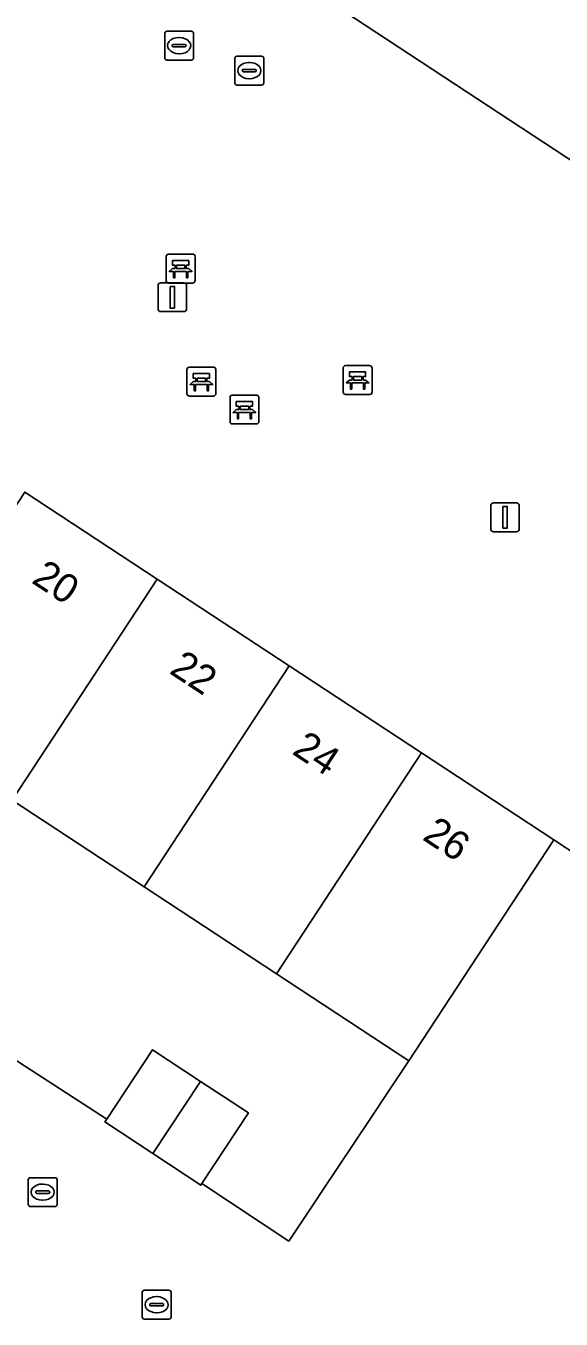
# Model space of a CAD drawing. Extents: x 159279 to 160377, y 384531 to 385888.
# Drawn here: x 159600.5 to 159619.07, y 385070.38 to 385115.23 of the extents above; entities that cross this region are included whole.
import ezdxf

# ---------------------------------------------------------------- set-up
doc = ezdxf.new("R2010")
doc.units = 0
for name, color, linetype in [('IMGEO_Bank', 7, 'Continuous'), ('IMGEO_Erf', 7, 'Continuous'), ('IMGEO_Hek', 7, 'Continuous'), ('IMGEO_Kolk', 7, 'Continuous'), ('IMGEO_Lichtmast', 7, 'Continuous'), ('IMGEO_Pand', 7, 'Continuous'), ('IMGEO_Pand_nummerreeks', 7, 'Continuous'), ('IMGEO_Rioolput', 7, 'Continuous'), ('IMGEO_Voetpad_open', 7, 'Continuous')]:
    doc.layers.add(name, color=color, linetype=linetype)

msp = doc.modelspace()

# ---------------------------------------------------------------- linework, layer by layer
at = {"layer": 'IMGEO_Bank'}
for p, q in [((159605.37, 385106.384), (159605.37, 385107.225)), ((159605.37, 385107.225), (159605.37, 385106.384)), ((159605.445, 385107.309), (159606.286, 385107.309)), ((159606.286, 385107.309), (159605.445, 385107.309)), ((159606.37, 385107.234), (159606.37, 385106.393)), ((159606.37, 385106.393), (159606.37, 385107.234)), ((159606.067, 385106.707), (159605.674, 385106.707)), ((159605.679, 385106.815), (159605.679, 385106.921)), ((159605.723, 385106.921), (159605.723, 385106.815)), ((159606.011, 385106.927), (159605.729, 385106.927)), ((159605.729, 385106.809), (159606.011, 385106.809)), ((159606.017, 385106.815), (159606.017, 385106.921)), ((159606.061, 385106.921), (159606.061, 385106.815)), ((159606.295, 385106.309), (159605.454, 385106.309)), ((159605.454, 385106.309), (159606.295, 385106.309)), ((159606.088, 385102.465), (159606.088, 385103.306)), ((159606.088, 385103.306), (159606.088, 385102.465)), ((159606.163, 385103.39), (159607.004, 385103.39)), ((159607.004, 385103.39), (159606.163, 385103.39)), ((159607.088, 385103.315), (159607.088, 385102.474)), ((159607.088, 385102.474), (159607.088, 385103.315)), ((159611.506, 385102.521), (159611.506, 385103.362)), ((159611.506, 385103.362), (159611.506, 385102.521)), ((159611.581, 385103.446), (159612.422, 385103.446)), ((159612.422, 385103.446), (159611.581, 385103.446)), ((159611.815, 385102.952), (159611.815, 385103.058)), ((159611.859, 385103.058), (159611.859, 385102.952)), ((159612.147, 385103.064), (159611.865, 385103.064)), ((159612.153, 385102.952), (159612.153, 385103.058)), ((159612.197, 385103.058), (159612.197, 385102.952)), ((159612.506, 385103.371), (159612.506, 385102.53)), ((159612.506, 385102.53), (159612.506, 385103.371)), ((159606.785, 385102.788), (159606.392, 385102.788)), ((159606.397, 385102.896), (159606.397, 385103.002)), ((159606.441, 385103.002), (159606.441, 385102.896)), ((159606.729, 385103.008), (159606.447, 385103.008)), ((159606.447, 385102.89), (159606.729, 385102.89)), ((159606.735, 385102.896), (159606.735, 385103.002)), ((159606.779, 385103.002), (159606.779, 385102.896)), ((159612.203, 385102.844), (159611.81, 385102.844)), ((159611.865, 385102.946), (159612.147, 385102.946)), ((159607.013, 385102.39), (159606.172, 385102.39)), ((159606.172, 385102.39), (159607.013, 385102.39)), ((159607.581, 385101.496), (159607.581, 385102.337)), ((159607.581, 385102.337), (159607.581, 385101.496)), ((159607.656, 385102.421), (159608.497, 385102.421)), ((159608.497, 385102.421), (159607.656, 385102.421)), ((159608.581, 385102.346), (159608.581, 385101.505)), ((159608.581, 385101.505), (159608.581, 385102.346)), ((159612.431, 385102.446), (159611.59, 385102.446)), ((159611.59, 385102.446), (159612.431, 385102.446)), ((159608.278, 385101.819), (159607.885, 385101.819)), ((159607.89, 385101.927), (159607.89, 385102.033)), ((159607.934, 385102.033), (159607.934, 385101.927)), ((159608.222, 385102.039), (159607.94, 385102.039)), ((159607.94, 385101.921), (159608.222, 385101.921)), ((159608.228, 385101.927), (159608.228, 385102.033)), ((159608.272, 385102.033), (159608.272, 385101.927)), ((159608.506, 385101.421), (159607.665, 385101.421)), ((159607.665, 385101.421), (159608.506, 385101.421))]:
    msp.add_line(p, q, dxfattribs=at)
for points in [[(159605.673, 385106.927), (159605.587, 385106.927), (159605.587, 385107.088), (159606.15, 385107.088), (159606.15, 385106.927), (159606.067, 385106.927)], [(159605.617, 385106.707), (159605.475, 385106.707), (159605.587, 385106.809), (159605.673, 385106.809)], [(159605.667, 385106.7), (159605.667, 385106.493), (159605.624, 385106.493), (159605.624, 385106.7)], [(159606.067, 385106.809), (159606.15, 385106.809), (159606.262, 385106.707), (159606.123, 385106.707)], [(159606.117, 385106.7), (159606.117, 385106.493), (159606.073, 385106.493), (159606.073, 385106.7)], [(159606.391, 385103.008), (159606.305, 385103.008), (159606.305, 385103.169), (159606.868, 385103.169), (159606.868, 385103.008), (159606.785, 385103.008)], [(159611.809, 385103.064), (159611.723, 385103.064), (159611.723, 385103.225), (159612.286, 385103.225), (159612.286, 385103.064), (159612.203, 385103.064)], [(159606.335, 385102.788), (159606.193, 385102.788), (159606.305, 385102.89), (159606.391, 385102.89)], [(159606.385, 385102.781), (159606.385, 385102.574), (159606.342, 385102.574), (159606.342, 385102.781)], [(159606.785, 385102.89), (159606.868, 385102.89), (159606.98, 385102.788), (159606.841, 385102.788)], [(159606.835, 385102.781), (159606.835, 385102.574), (159606.791, 385102.574), (159606.791, 385102.781)], [(159611.753, 385102.844), (159611.611, 385102.844), (159611.723, 385102.946), (159611.809, 385102.946)], [(159611.803, 385102.837), (159611.803, 385102.63), (159611.76, 385102.63), (159611.76, 385102.837)], [(159612.203, 385102.946), (159612.286, 385102.946), (159612.398, 385102.844), (159612.259, 385102.844)], [(159612.253, 385102.837), (159612.253, 385102.63), (159612.209, 385102.63), (159612.209, 385102.837)], [(159607.884, 385102.039), (159607.798, 385102.039), (159607.798, 385102.2), (159608.361, 385102.2), (159608.361, 385102.039), (159608.278, 385102.039)], [(159607.828, 385101.819), (159607.686, 385101.819), (159607.798, 385101.921), (159607.884, 385101.921)], [(159607.878, 385101.812), (159607.878, 385101.605), (159607.835, 385101.605), (159607.835, 385101.812)], [(159608.278, 385101.921), (159608.361, 385101.921), (159608.473, 385101.819), (159608.334, 385101.819)], [(159608.328, 385101.812), (159608.328, 385101.605), (159608.284, 385101.605), (159608.284, 385101.812)]]:
    msp.add_lwpolyline(points, dxfattribs=at)
for centre, radius, start, end in [((159605.448, 385107.231), 0.0779, 92.4484, 184.2845), ((159605.448, 385107.231), 0.0779, 92.4484, 184.2845), ((159606.292, 385107.231), 0.0779, 2.4484, 94.2845), ((159606.292, 385107.231), 0.0779, 2.4484, 94.2845), ((159605.617, 385106.7), 0.00671, 2.8957, 87.1043), ((159605.674, 385106.7), 0.00671, 92.8957, 177.1043), ((159605.672, 385106.92), 0.00671, 2.8957, 87.1043), ((159605.672, 385106.816), 0.00671, 272.8957, 357.1043), ((159605.729, 385106.92), 0.00671, 92.8957, 177.1043), ((159605.729, 385106.816), 0.00671, 182.8957, 267.1043), ((159606.011, 385106.92), 0.00671, 2.8957, 87.1043), ((159606.011, 385106.816), 0.00671, 272.8957, 357.1043), ((159606.068, 385106.92), 0.00671, 92.8957, 177.1043), ((159606.068, 385106.816), 0.00671, 182.8957, 267.1043), ((159606.066, 385106.7), 0.00671, 2.8957, 87.1043), ((159606.123, 385106.7), 0.00671, 92.8957, 177.1043), ((159605.448, 385106.387), 0.0779, 182.4484, 274.2845), ((159605.448, 385106.387), 0.0779, 182.4484, 274.2845), ((159606.292, 385106.387), 0.0779, 272.4484, 4.2845), ((159606.292, 385106.387), 0.0779, 272.4484, 4.2845), ((159606.166, 385103.312), 0.0779, 92.4484, 184.2845), ((159606.166, 385103.312), 0.0779, 92.4484, 184.2845), ((159607.01, 385103.312), 0.0779, 2.4484, 94.2845), ((159607.01, 385103.312), 0.0779, 2.4484, 94.2845), ((159611.584, 385103.368), 0.0779, 92.4484, 184.2845), ((159611.584, 385103.368), 0.0779, 92.4484, 184.2845), ((159611.808, 385103.057), 0.00671, 2.8957, 87.1043), ((159611.865, 385103.057), 0.00671, 92.8957, 177.1043), ((159612.147, 385103.057), 0.00671, 2.8957, 87.1043), ((159612.204, 385103.057), 0.00671, 92.8957, 177.1043), ((159612.428, 385103.368), 0.0779, 2.4484, 94.2845), ((159612.428, 385103.368), 0.0779, 2.4484, 94.2845), ((159606.335, 385102.781), 0.00671, 2.8957, 87.1043), ((159606.392, 385102.781), 0.00671, 92.8957, 177.1043), ((159606.39, 385103.001), 0.00671, 2.8957, 87.1043), ((159606.39, 385102.897), 0.00671, 272.8957, 357.1043), ((159606.447, 385103.001), 0.00671, 92.8957, 177.1043), ((159606.447, 385102.897), 0.00671, 182.8957, 267.1043), ((159606.729, 385103.001), 0.00671, 2.8957, 87.1043), ((159606.729, 385102.897), 0.00671, 272.8957, 357.1043), ((159606.786, 385103.001), 0.00671, 92.8957, 177.1043), ((159606.786, 385102.897), 0.00671, 182.8957, 267.1043), ((159606.784, 385102.781), 0.00671, 2.8957, 87.1043), ((159606.841, 385102.781), 0.00671, 92.8957, 177.1043), ((159611.753, 385102.837), 0.00671, 2.8957, 87.1043), ((159611.81, 385102.837), 0.00671, 92.8957, 177.1043), ((159611.808, 385102.953), 0.00671, 272.8957, 357.1043), ((159611.865, 385102.953), 0.00671, 182.8957, 267.1043), ((159612.147, 385102.953), 0.00671, 272.8957, 357.1043), ((159612.204, 385102.953), 0.00671, 182.8957, 267.1043), ((159612.202, 385102.837), 0.00671, 2.8957, 87.1043), ((159612.259, 385102.837), 0.00671, 92.8957, 177.1043), ((159606.166, 385102.468), 0.0779, 182.4484, 274.2845), ((159606.166, 385102.468), 0.0779, 182.4484, 274.2845), ((159607.01, 385102.468), 0.0779, 272.4484, 4.2845), ((159607.01, 385102.468), 0.0779, 272.4484, 4.2845), ((159607.659, 385102.343), 0.0779, 92.4484, 184.2845), ((159607.659, 385102.343), 0.0779, 92.4484, 184.2845), ((159608.503, 385102.343), 0.0779, 2.4484, 94.2845), ((159608.503, 385102.343), 0.0779, 2.4484, 94.2845), ((159611.584, 385102.524), 0.0779, 182.4484, 274.2845), ((159611.584, 385102.524), 0.0779, 182.4484, 274.2845), ((159612.428, 385102.524), 0.0779, 272.4484, 4.2845), ((159612.428, 385102.524), 0.0779, 272.4484, 4.2845), ((159607.828, 385101.812), 0.00671, 2.8957, 87.1043), ((159607.885, 385101.812), 0.00671, 92.8957, 177.1043), ((159607.883, 385102.032), 0.00671, 2.8957, 87.1043), ((159607.883, 385101.928), 0.00671, 272.8957, 357.1043), ((159607.94, 385102.032), 0.00671, 92.8957, 177.1043), ((159607.94, 385101.928), 0.00671, 182.8957, 267.1043), ((159608.222, 385102.032), 0.00671, 2.8957, 87.1043), ((159608.222, 385101.928), 0.00671, 272.8957, 357.1043), ((159608.279, 385102.032), 0.00671, 92.8957, 177.1043), ((159608.279, 385101.928), 0.00671, 182.8957, 267.1043), ((159608.277, 385101.812), 0.00671, 2.8957, 87.1043), ((159608.334, 385101.812), 0.00671, 92.8957, 177.1043), ((159607.659, 385101.499), 0.0779, 182.4484, 274.2845), ((159607.659, 385101.499), 0.0779, 182.4484, 274.2845), ((159608.503, 385101.499), 0.0779, 272.4484, 4.2845), ((159608.503, 385101.499), 0.0779, 272.4484, 4.2845)]:
    msp.add_arc(centre, radius, start, end, dxfattribs=at)
at = {"layer": 'IMGEO_Erf'}
for points in [[(159597.623, 385080.991), (159603.306, 385077.318), (159604.892, 385079.724), (159606.556, 385078.628), (159608.22, 385077.531), (159606.606, 385075.082), (159609.619, 385073.089), (159613.784, 385079.344), (159609.195, 385082.356), (159604.606, 385085.367), (159600.018, 385088.379)], [(159621.083, 385085.514), (159618.81, 385087.007), (159613.784, 385079.344), (159609.619, 385073.089), (159606.606, 385075.082), (159606.569, 385075.026), (159604.905, 385076.122), (159603.241, 385077.219), (159603.306, 385077.318), (159597.623, 385080.991)]]:
    msp.add_lwpolyline(points, dxfattribs=at)
at = {"layer": 'IMGEO_Hek'}
for points in [[(159603.306, 385077.318), (159597.623, 385080.991)], [(159613.784, 385079.344), (159609.619, 385073.089), (159606.606, 385075.082)]]:
    msp.add_lwpolyline(points, dxfattribs=at)
at = {"layer": 'IMGEO_Kolk'}
for p, q in [((159607.749, 385113.248), (159607.749, 385114.1)), ((159607.824, 385114.174), (159608.676, 385114.174)), ((159608.237, 385113.954), (159608.262, 385113.954)), ((159608.75, 385114.1), (159608.75, 385113.248)), ((159608.008, 385113.668), (159608.008, 385113.68)), ((159608.446, 385113.631), (159608.048, 385113.631)), ((159608.051, 385113.717), (159608.449, 385113.717)), ((159608.26, 385113.394), (159608.235, 385113.394)), ((159608.492, 385113.68), (159608.492, 385113.668)), ((159608.676, 385113.174), (159607.824, 385113.174)), ((159604.536, 385070.458), (159604.536, 385071.31)), ((159604.611, 385071.384), (159605.463, 385071.384)), ((159605.537, 385071.31), (159605.537, 385070.458)), ((159604.795, 385070.878), (159604.795, 385070.89)), ((159605.233, 385070.841), (159604.835, 385070.841)), ((159604.838, 385070.927), (159605.236, 385070.927)), ((159605.024, 385071.164), (159605.049, 385071.164)), ((159605.279, 385070.89), (159605.279, 385070.878)), ((159605.463, 385070.384), (159604.611, 385070.384)), ((159605.047, 385070.604), (159605.022, 385070.604))]:
    msp.add_line(p, q, dxfattribs=at)
for points in [[(159607.749, 385113.248), (159607.749, 385114.1)], [(159607.824, 385114.174), (159608.676, 385114.174)], [(159608.75, 385114.1), (159608.75, 385113.248)], [(159608.676, 385113.174), (159607.824, 385113.174)], [(159604.536, 385070.458), (159604.536, 385071.31)], [(159604.611, 385071.384), (159605.463, 385071.384)], [(159605.537, 385071.31), (159605.537, 385070.458)], [(159605.463, 385070.384), (159604.611, 385070.384)]]:
    msp.add_lwpolyline(points, dxfattribs=at)
for centre, radius, start, end in [((159607.826, 385114.098), 0.0765, 91.552, 178.448), ((159607.826, 385114.098), 0.0765, 91.552, 178.448), ((159608.674, 385114.098), 0.0765, 1.552, 88.448), ((159608.674, 385114.098), 0.0765, 1.552, 88.448), ((159608.048, 385113.677), 0.0403, 85.8775, 175.7526), ((159608.045, 385113.667), 0.0366, 178.938, 274.7102), ((159608.449, 385113.674), 0.043, 264.8664, 352.4533), ((159608.453, 385113.679), 0.0386, 1.7309, 96.639), ((159607.826, 385113.25), 0.0765, 181.552, 268.448), ((159607.826, 385113.25), 0.0765, 181.552, 268.448), ((159608.674, 385113.25), 0.0765, 271.552, 358.448), ((159608.674, 385113.25), 0.0765, 271.552, 358.448), ((159604.613, 385071.308), 0.0765, 91.552, 178.448), ((159604.613, 385071.308), 0.0765, 91.552, 178.448), ((159605.461, 385071.308), 0.0765, 1.552, 88.448), ((159605.461, 385071.308), 0.0765, 1.552, 88.448), ((159604.835, 385070.887), 0.0403, 85.8775, 175.7526), ((159604.832, 385070.877), 0.0366, 178.938, 274.7102), ((159605.236, 385070.884), 0.043, 264.8664, 352.4533), ((159605.24, 385070.889), 0.0386, 1.7309, 96.639), ((159604.613, 385070.46), 0.0765, 181.552, 268.448), ((159604.613, 385070.46), 0.0765, 181.552, 268.448), ((159605.461, 385070.46), 0.0765, 271.552, 358.448), ((159605.461, 385070.46), 0.0765, 271.552, 358.448)]:
    msp.add_arc(centre, radius, start, end, dxfattribs=at)
for centre, major_axis, ratio, start_param, end_param in [((159608.236, 385113.674), (-0.387, 0.002), 0.722429, 4.712389, 7.853982), ((159608.261, 385113.674), (-0.39, 0.002), 0.717154, 1.570796, 4.712389), ((159605.023, 385070.884), (-0.387, 0.002), 0.722429, 4.712389, 7.853982), ((159605.048, 385070.884), (-0.39, 0.002), 0.717154, 1.570796, 4.712389)]:
    msp.add_ellipse(centre, major_axis=major_axis, ratio=ratio, start_param=start_param, end_param=end_param, dxfattribs=at)
at = {"layer": 'IMGEO_Lichtmast'}
for p, q in [((159605.084, 385105.416), (159605.084, 385106.216)), ((159605.084, 385106.216), (159605.084, 385105.416)), ((159605.184, 385106.316), (159605.974, 385106.316)), ((159605.974, 385106.316), (159605.184, 385106.316)), ((159606.074, 385106.216), (159606.074, 385105.416)), ((159606.074, 385105.416), (159606.074, 385106.216)), ((159605.974, 385105.316), (159605.184, 385105.316)), ((159605.184, 385105.316), (159605.974, 385105.316)), ((159616.625, 385097.786), (159616.625, 385098.586)), ((159616.625, 385098.586), (159616.625, 385097.786)), ((159616.725, 385098.686), (159617.515, 385098.686)), ((159617.515, 385098.686), (159616.725, 385098.686)), ((159617.615, 385098.586), (159617.615, 385097.786)), ((159617.615, 385097.786), (159617.615, 385098.586)), ((159617.515, 385097.686), (159616.725, 385097.686)), ((159616.725, 385097.686), (159617.515, 385097.686))]:
    msp.add_line(p, q, dxfattribs=at)
for points in [[(159605.504, 385106.191), (159605.654, 385106.191), (159605.654, 385105.441), (159605.504, 385105.441), (159605.504, 385106.191)], [(159617.045, 385098.561), (159617.195, 385098.561), (159617.195, 385097.811), (159617.045, 385097.811), (159617.045, 385098.561)]]:
    msp.add_lwpolyline(points, dxfattribs=at)
for centre, start, end in [((159605.184, 385106.216), 90, 180), ((159605.184, 385106.216), 90, 180), ((159605.974, 385106.216), 0, 90), ((159605.974, 385106.216), 360, 90), ((159605.184, 385105.416), 180, 270), ((159605.184, 385105.416), 180, 270), ((159605.974, 385105.416), 270, 0), ((159605.974, 385105.416), 270, 0), ((159616.725, 385098.586), 90, 180), ((159616.725, 385098.586), 90, 180), ((159617.515, 385098.586), 0, 90), ((159617.515, 385098.586), 360, 90), ((159616.725, 385097.786), 180, 270), ((159616.725, 385097.786), 180, 270), ((159617.515, 385097.786), 270, 0), ((159617.515, 385097.786), 270, 0)]:
    msp.add_arc(centre, 0.1, start, end, dxfattribs=at)
at = {"layer": 'IMGEO_Pand'}
msp.add_lwpolyline([(159628.974, 385129.136), (159620.204, 385134.886), (159608.799, 385117.538), (159630.864, 385103.045), (159634.946, 385109.213), (159633.852, 385109.979), (159638.288, 385116.823), (159640.072, 385119.577)], dxfattribs=at)
for points in [[(159605.049, 385096.045), (159600.461, 385099.058), (159595.429, 385091.391), (159600.018, 385088.379)], [(159609.637, 385093.032), (159605.049, 385096.045), (159600.018, 385088.379), (159604.606, 385085.367)], [(159614.224, 385090.019), (159609.637, 385093.032), (159604.606, 385085.367), (159609.195, 385082.356)], [(159618.81, 385087.007), (159614.224, 385090.019), (159609.195, 385082.356), (159613.784, 385079.344)], [(159606.556, 385078.628), (159604.892, 385079.724), (159603.306, 385077.318), (159603.241, 385077.219), (159604.905, 385076.122)], [(159608.22, 385077.531), (159606.556, 385078.628), (159604.905, 385076.122), (159606.569, 385075.026), (159606.606, 385075.082)]]:
    msp.add_lwpolyline(points, close=True, dxfattribs=at)
at = {"layer": 'IMGEO_Rioolput'}
for p, q in [((159605.315, 385114.113), (159605.315, 385114.965)), ((159605.39, 385115.039), (159606.242, 385115.039)), ((159605.803, 385114.819), (159605.828, 385114.819)), ((159606.316, 385114.965), (159606.316, 385114.113)), ((159605.574, 385114.533), (159605.574, 385114.545)), ((159606.012, 385114.496), (159605.614, 385114.496)), ((159605.617, 385114.582), (159606.015, 385114.582)), ((159605.826, 385114.259), (159605.801, 385114.259)), ((159606.058, 385114.545), (159606.058, 385114.533)), ((159606.242, 385114.039), (159605.39, 385114.039)), ((159600.657, 385075.288), (159601.509, 385075.288)), ((159600.582, 385074.362), (159600.582, 385075.214)), ((159600.884, 385074.831), (159601.282, 385074.831)), ((159601.07, 385075.068), (159601.095, 385075.068)), ((159601.583, 385075.214), (159601.583, 385074.362)), ((159600.841, 385074.782), (159600.841, 385074.794)), ((159601.279, 385074.745), (159600.881, 385074.745)), ((159601.093, 385074.508), (159601.068, 385074.508)), ((159601.325, 385074.794), (159601.325, 385074.782)), ((159601.509, 385074.288), (159600.657, 385074.288))]:
    msp.add_line(p, q, dxfattribs=at)
for points in [[(159605.315, 385114.113), (159605.315, 385114.965)], [(159605.39, 385115.039), (159606.242, 385115.039)], [(159606.316, 385114.965), (159606.316, 385114.113)], [(159606.242, 385114.039), (159605.39, 385114.039)], [(159600.657, 385075.288), (159601.509, 385075.288)], [(159600.582, 385074.362), (159600.582, 385075.214)], [(159601.583, 385075.214), (159601.583, 385074.362)], [(159601.509, 385074.288), (159600.657, 385074.288)]]:
    msp.add_lwpolyline(points, dxfattribs=at)
for centre, radius, start, end in [((159605.392, 385114.963), 0.0765, 91.552, 178.448), ((159605.392, 385114.963), 0.0765, 91.552, 178.448), ((159606.24, 385114.963), 0.0765, 1.552, 88.448), ((159606.24, 385114.963), 0.0765, 1.552, 88.448), ((159605.614, 385114.542), 0.0403, 85.8775, 175.7526), ((159605.611, 385114.532), 0.0366, 178.938, 274.7102), ((159606.015, 385114.539), 0.043, 264.8664, 352.4533), ((159606.019, 385114.544), 0.0386, 1.7309, 96.639), ((159605.392, 385114.115), 0.0765, 181.552, 268.448), ((159605.392, 385114.115), 0.0765, 181.552, 268.448), ((159606.24, 385114.115), 0.0765, 271.552, 358.448), ((159606.24, 385114.115), 0.0765, 271.552, 358.448), ((159600.659, 385075.212), 0.0765, 91.552, 178.448), ((159600.659, 385075.212), 0.0765, 91.552, 178.448), ((159601.507, 385075.212), 0.0765, 1.552, 88.448), ((159601.507, 385075.212), 0.0765, 1.552, 88.448), ((159600.881, 385074.791), 0.0403, 85.8775, 175.7526), ((159601.286, 385074.793), 0.0386, 1.7309, 96.639), ((159600.659, 385074.364), 0.0765, 181.552, 268.448), ((159600.659, 385074.364), 0.0765, 181.552, 268.448), ((159600.878, 385074.781), 0.0366, 178.938, 274.7102), ((159601.282, 385074.788), 0.043, 264.8664, 352.4533), ((159601.507, 385074.364), 0.0765, 271.552, 358.448), ((159601.507, 385074.364), 0.0765, 271.552, 358.448)]:
    msp.add_arc(centre, radius, start, end, dxfattribs=at)
for centre, major_axis, ratio, start_param, end_param in [((159605.802, 385114.539), (-0.387, 0.002), 0.722429, 4.712389, 7.853982), ((159605.827, 385114.539), (-0.39, 0.002), 0.717154, 1.570796, 4.712389), ((159601.069, 385074.788), (-0.387, 0.002), 0.722429, 4.712389, 7.853982), ((159601.094, 385074.788), (-0.39, 0.002), 0.717154, 1.570796, 4.712389)]:
    msp.add_ellipse(centre, major_axis=major_axis, ratio=ratio, start_param=start_param, end_param=end_param, dxfattribs=at)
at = {"layer": 'IMGEO_Voetpad_open'}
for points in [[(159640.072, 385119.577), (159638.288, 385116.823), (159633.852, 385109.979), (159634.946, 385109.213), (159630.864, 385103.045), (159608.799, 385117.538), (159620.204, 385134.886), (159628.974, 385129.136)], [(159600.461, 385099.058), (159605.049, 385096.045), (159609.637, 385093.032), (159614.224, 385090.019), (159618.81, 385087.007), (159621.083, 385085.514), (159629.049, 385097.508), (159629.43, 385097.251), (159633.373, 385094.661), (159637.7, 385091.818), (159642.028, 385088.975), (159646.355, 385086.133), (159650.682, 385083.29)]]:
    msp.add_lwpolyline(points, dxfattribs=at)

# ---------------------------------------------------------------- texts
at = {"layer": 'IMGEO_Pand_nummerreeks'}
for s, p in [('20', (159600.66, 385095.937)), ('22', (159605.438, 385092.799)), ('24', (159609.697, 385090.002)), ('26', (159614.218, 385087.032))]:
    msp.add_text(s, height=1, rotation=326.7054, dxfattribs=at).set_placement(p)

doc.saveas('drawing.dxf')
